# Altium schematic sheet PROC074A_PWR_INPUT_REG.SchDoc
size 431 x 279 mm; Date: Not shown in title block; ApprovedBy: Not shown in title block; CheckedBy: Not shown in title block; Author: Not shown in title block; CompanyName: Not shown in title block; Engineer: Not shown in title block; Organization: Not shown in title block; Address1: Not shown in title block; Address2: Not shown in title block; Address3: Not shown in title block; Address4: Not shown in title block; DocumentNumber: 1; Revision: Use project parameter SCH_Rev; SheetNumber: 5; SheetTotal: 22; PageSetup: Record=PageOptions¦CenterHorizontal=True¦CenterVertical=True¦PrintScale=1.00¦XCorrection=1.00¦YCorrection=1.00¦PrintKind=0¦BorderSize=5000000¦LeftOffset=0¦BottomOffset=0¦Orientation=2¦PaperLength=1000¦PaperWidth=1000¦Scale=100¦PaperSource=15¦PrintQuality=600¦MediaType=1¦DitherType=10¦PaperKind=Letter¦PrintScaleMode=1
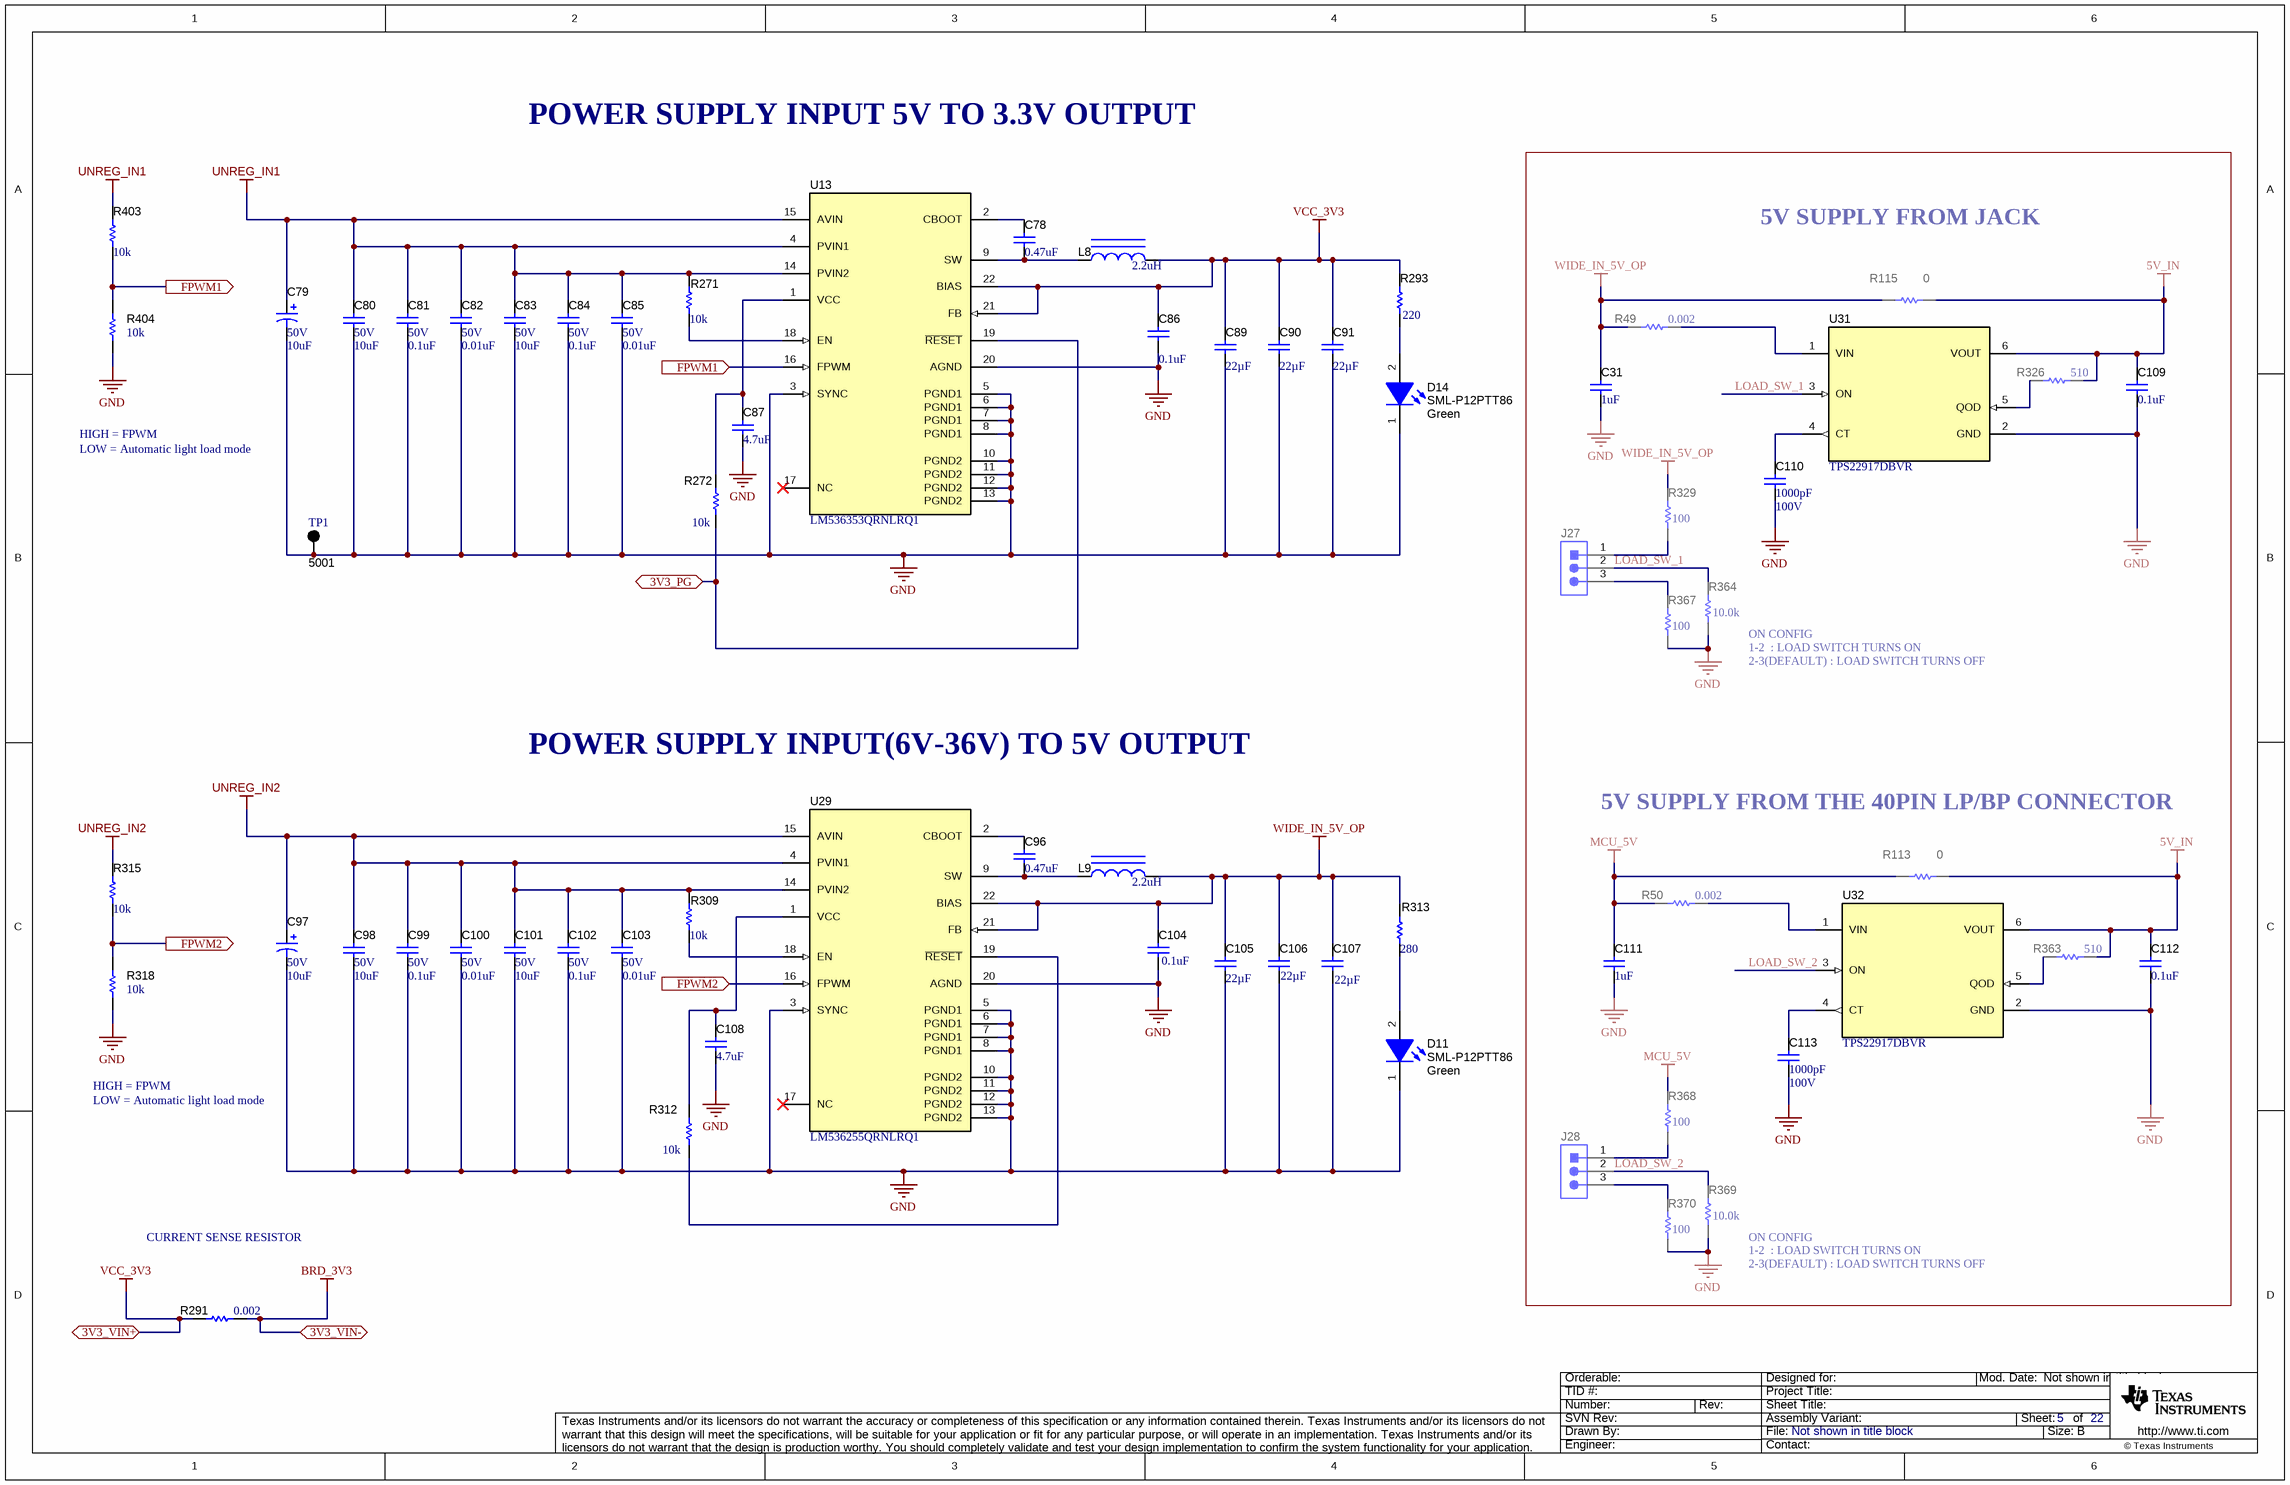
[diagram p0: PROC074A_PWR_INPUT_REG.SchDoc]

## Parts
C31  ValueDisplayed: 1uF  [0603]  (hidden comment: GCM188R71C105KA64D)
C78  ValueDisplayed: 0.47uF  [0402]  (hidden comment: JMK105B7474KVHF)
C79  VDC_V: 50V  ValueDisplayed: 10uF  [SM_RADIAL_C]  (hidden comment: EEE-FK1H100UR)
C80  VDC_V: 50V  ValueDisplayed: 10uF  [1210_270]  (hidden comment: GRM32ER71H106MA12)
C81  VDC_V: 50V  ValueDisplayed: 0.1uF  [1210]  (hidden comment: C1210C104K5RACTU)
C82  VDC_V: 50V  ValueDisplayed: 0.01uF  [0805_HV]  (hidden comment: C0805C103K5RACTU)
C83  VDC_V: 50V  ValueDisplayed: 10uF  [1210_270]  (hidden comment: GRM32ER71H106MA12)
C84  VDC_V: 50V  ValueDisplayed: 0.1uF  [1210]  (hidden comment: C1210C104K5RACTU)
C85  VDC_V: 50V  ValueDisplayed: 0.01uF  [0805_HV]  (hidden comment: C0805C103K5RACTU)
C86  ValueDisplayed: 0.1uF  [0402]  (hidden comment: 0402YC104KAT2A)
C87  ValueDisplayed: 4.7uF  [0805_HV]  (hidden comment: C2012X7R1E475K125AB)
C89  ValueDisplayed: 22µF  [1210_270]  (hidden comment: CL32B226KOJNFNE)
C90  ValueDisplayed: 22µF  [1210_270]  (hidden comment: CL32B226KOJNFNE)
C91  ValueDisplayed: 22µF  [1210_270]  (hidden comment: CL32B226KOJNFNE)
C96  ValueDisplayed: 0.47uF  [0402]  (hidden comment: JMK105B7474KVHF)
C97  VDC_V: 50V  ValueDisplayed: 10uF  [SM_RADIAL_C]  (hidden comment: EEE-FK1H100UR)
C98  VDC_V: 50V  ValueDisplayed: 10uF  [1210_270]  (hidden comment: GRM32ER71H106MA12)
C99  VDC_V: 50V  ValueDisplayed: 0.1uF  [1210]  (hidden comment: C1210C104K5RACTU)
C100  VDC_V: 50V  ValueDisplayed: 0.01uF  [0805_HV]  (hidden comment: C0805C103K5RACTU)
C101  VDC_V: 50V  ValueDisplayed: 10uF  [1210_270]  (hidden comment: GRM32ER71H106MA12)
C102  VDC_V: 50V  ValueDisplayed: 0.1uF  [1210]  (hidden comment: C1210C104K5RACTU)
C103  VDC_V: 50V  ValueDisplayed: 0.01uF  [0805_HV]  (hidden comment: C0805C103K5RACTU)
C104  ValueDisplayed: 0.1uF  [0402]  (hidden comment: 0402YC104KAT2A)
C105  ValueDisplayed: 22µF  [1210_270]  (hidden comment: CL32B226KOJNFNE)
C106  ValueDisplayed: 22µF  [1210_270]  (hidden comment: CL32B226KOJNFNE)
C107  ValueDisplayed: 22µF  [1210_270]  (hidden comment: CL32B226KOJNFNE)
C108  ValueDisplayed: 4.7uF  [0805_HV]  (hidden comment: C2012X7R1E475K125AB)
C109  ValueDisplayed: 0.1uF  [0603]  (hidden comment: C0603C104J3RACTU)
C110  VDC_V: 100V  ValueDisplayed: 1000pF  [0402]  (hidden comment: CGA2B3X7S2A102K050BB)
C111  ValueDisplayed: 1uF  [0603]  (hidden comment: GCM188R71C105KA64D)
C112  ValueDisplayed: 0.1uF  [0603]  (hidden comment: C0603C104J3RACTU)
C113  VDC_V: 100V  ValueDisplayed: 1000pF  [0402]  (hidden comment: CGA2B3X7S2A102K050BB)
D11  SML-P12PTT86  value Green  [SML-P1_GREEN]
D14  SML-P12PTT86  value Green  [SML-P1_GREEN]
J27  22284033  [Molex_0022284033]  (value not drawn)
J28  22284033  [Molex_0022284033]  (value not drawn)
L8  ValueDisplayed: 2.2uH  [XAL5030]  (hidden comment: XAL5030-222MEB)
L9  ValueDisplayed: 2.2uH  [XAL5030]  (hidden comment: XAL5030-222MEB)
R49  ValueDisplayed: 0.002  [1206]  (hidden comment: PMR18EZPFV2L00)
R50  ValueDisplayed: 0.002  [1206]  (hidden comment: PMR18EZPFV2L00)
R113  ValueDisplayed: 0  [2010]  (hidden comment: CRCW20100000Z0EF)
R115  ValueDisplayed: 0  [2010]  (hidden comment: CRCW20100000Z0EF)
R271  ValueDisplayed: 10k  [0402]  (hidden comment: CRCW040210K0JNED)
R272  ValueDisplayed: 10k  [0402]  (hidden comment: CRCW040210K0JNED)
R291  ValueDisplayed: 0.002  [1206]  (hidden comment: PMR18EZPFV2L00)
R293  ValueDisplayed: 220  [0402]  (hidden comment: CRCW0402220RJNED)
R309  ValueDisplayed: 10k  [0402]  (hidden comment: CRCW040210K0JNED)
R312  ValueDisplayed: 10k  [0402]  (hidden comment: CRCW040210K0JNED)
R313  ValueDisplayed: 280  [0402]  (hidden comment: CRCW0402280RFKED)
R315  ValueDisplayed: 10k  [0402]  (hidden comment: CRCW040210K0JNED)
R318  ValueDisplayed: 10k  [0402]  (hidden comment: CRCW040210K0JNED)
R326  ValueDisplayed: 510  [0402]  (hidden comment: CRCW0402510RJNED)
R329  ValueDisplayed: 100  [0402]  (hidden comment: ERJ-2GEJ101X)
R363  ValueDisplayed: 510  [0402]  (hidden comment: CRCW0402510RJNED)
R364  ValueDisplayed: 10.0k  [0402]  (hidden comment: CRCW040210K0FKED)
R367  ValueDisplayed: 100  [0402]  (hidden comment: ERJ-2GEJ101X)
R368  ValueDisplayed: 100  [0402]  (hidden comment: ERJ-2GEJ101X)
R369  ValueDisplayed: 10.0k  [0402]  (hidden comment: CRCW040210K0FKED)
R370  ValueDisplayed: 100  [0402]  (hidden comment: ERJ-2GEJ101X)
R403  ValueDisplayed: 10k  [0402]  (hidden comment: CRCW040210K0JNED)
R404  ValueDisplayed: 10k  [0402]  (hidden comment: CRCW040210K0JNED)
TP1  5001  [Keystone5001]
U13  LM536353QRNLRQ1  [RNL0022A]
U29  LM536255QRNLRQ1  [RNL0022A]
U31  TPS22917DBVR  [DBV0006A_L]
U32  TPS22917DBVR  [DBV0006A_L]

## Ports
3V3_PG, 3V3_VIN+, 3V3_VIN-, FPWM1 (in), FPWM1 (out), FPWM2 (in), FPWM2 (out)

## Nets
5V_IN: C109.1 C112.1 R113.2 R115.2 R326.1 R363.1 U31.6(VOUT) U32.6(VOUT)
BRD_3V3: R291.2 ; port 3V3_VIN-
GND: C31.2 C79.2(-) C80.2 C81.2 C82.2 C83.2 C84.2 C85.2 C86.2 C87.2 C89.2 C90.2 C91.2 C97.2(-) C98.2 C99.2 C100.2 C101.2 C102.2 C103.2 C104.2 C105.2 C106.2 C107.2 C108.2 C109.2 C110.2 C111.2 C112.2 C113.2 D11.1(K) D14.1(K) R318.1 R364.1 R367.1 R369.1 R370.1 R404.1 TP1.1 U13.3(SYNC) U13.5(PGND1) U13.6(PGND1) U13.7(PGND1) U13.8(PGND1) U13.10(PGND2) U13.11(PGND2) U13.12(PGND2) U13.13(PGND2) U13.20(AGND) U29.3(SYNC) U29.5(PGND1) U29.6(PGND1) U29.7(PGND1) U29.8(PGND1) U29.10(PGND2) U29.11(PGND2) U29.12(PGND2) U29.13(PGND2) U29.20(AGND) U31.2(GND) U32.2(GND)
MCU_5V: C111.1 R50.1 R113.1 R368.2
UNREG_IN1: C79.1(+) C80.1 C81.1 C82.1 C83.1 C84.1 C85.1 R271.2 R403.2 U13.4(PVIN1) U13.14(PVIN2) U13.15(AVIN)
UNREG_IN2: C97.1(+) C98.1 C99.1 C100.1 C101.1 C102.1 C103.1 R309.2 R315.2 U29.4(PVIN1) U29.14(PVIN2) U29.15(AVIN)
VCC_3V3: C86.1 C89.1 C90.1 C91.1 L8.2 R291.1 R293.2 U13.21(FB) U13.22(BIAS) ; port 3V3_VIN+
WIDE_IN_5V_OP: C31.1 C104.1 C105.1 C106.1 C107.1 L9.2 R49.1 R115.1 R313.2 R329.2 U29.21(FB) U29.22(BIAS)
3V3_PG: R272.2 U13.19(~{RESET}) ; port 3V3_PG
FPWM1: R403.1 R404.2 U13.16(FPWM) ; port FPWM1
FPWM2: R315.1 R318.2 U29.16(FPWM) ; port FPWM2
LOAD_SW_1: J27.2 R364.2 U31.3(ON)
LOAD_SW_2: J28.2 R369.2 U32.3(ON)
NetC78_1: C78.1 U13.2(CBOOT)
NetC78_2: C78.2 L8.1 U13.9(SW)
NetC87_1: C87.1 R272.1 U13.1(VCC)
NetC96_1: C96.1 U29.2(CBOOT)
NetC96_2: C96.2 L9.1 U29.9(SW)
NetC108_1: C108.1 R312.1 U29.1(VCC)
NetC110_1: C110.1 U31.4(CT)
NetC113_1: C113.1 U32.4(CT)
NetD11_2: D11.2(A) R313.1
NetD14_2: D14.2(A) R293.1
NetJ27_1: J27.1 R329.1
NetJ27_3: J27.3 R367.2
NetJ28_1: J28.1 R368.1
NetJ28_3: J28.3 R370.2
NetR49_2: R49.2 U31.1(VIN)
NetR50_2: R50.2 U32.1(VIN)
NetR271_1: R271.1 U13.18(EN)
NetR309_1: R309.1 U29.18(EN)
NetR312_2: R312.2 U29.19(~{RESET})
NetR326_2: R326.2 U31.5(QOD)
NetR363_2: R363.2 U32.5(QOD)

Not connected (* = marked no-connect by the designer): U13 17(NC)*; U29 17(NC)*

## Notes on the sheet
- POWER SUPPLY INPUT 5V TO 3.3V OUTPUT
- 5V SUPPLY FROM JACK
- HIGH = FPWM
- LOW = Automatic light load mode
- (near R364) ON CONFIG
- (near R364) 2-3(DEFAULT) : LOAD SWITCH TURNS OFF
- (near R364) 1-2  : LOAD SWITCH TURNS ON
- POWER SUPPLY INPUT(6V-36V) TO 5V OUTPUT
- 5V SUPPLY FROM THE 40PIN LP/BP CONNECTOR
- CURRENT SENSE RESISTOR
- (near R369) ON CONFIG
- (near R369) 2-3(DEFAULT) : LOAD SWITCH TURNS OFF
- (near R369) 1-2  : LOAD SWITCH TURNS ON

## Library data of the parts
C31 C111 = CMP-0007136-5: CAP, CERM, 1 uF, 16 V, +/- 10%, X7R, AEC-Q200 Grade 1, 0603; Manufacturer: MuRata; TaMin_C: -55°C; Polarized: N; SizeAreaWB_mm2: 4.68; Value1: Unknown; U/M: EA; Value: 1uF; TaMax_C: 125°C; SizeZ_mm: 1; SizeX_mm: 1.6; SizeY_mm: 0.8; Value2: 16V; SizeArea_mm2: 1.28; CompType: Capacitor; AEC Qualified: Y; Cap_F: 1µF; AEC Category: Q200
C78 C96 = CMP-0006717-2: CAP, CERM, 0.47 uF, 6.3 V, +/- 10%, X7R, 0402; Manufacturer: Taiyo Yuden; TaMin_C: -55°C; Polarized: N; SizeAreaWB_mm2: 3; Value1: Unknown; U/M: EA; Value: 0.47uF; TaMax_C: 125°C; SizeZ_mm: 0.6; SizeX_mm: 1; SizeY_mm: 0.5; Value2: 6.3V; CompType: Capacitor; Cap_F: 470nF; AEC Category: Q200
C79 C97 = CMP-0011176-2: CAP, AL, 10 uF, 50 V, +/- 20%, 1.52 ohm, AEC-Q200 Grade 2, SMD; Manufacturer: Panasonic; TaMin_C: -55°C; ESR_ohm: 1.52; Polarized: Y; SizeAreaWB_mm2: 62.05; U/M: EA; Value: 10uF; TaMax_C: 105°C; SizeZ_mm: 5.4; SizeX_mm: 6.5; SizeY_mm: 5.3; Cap_Case: C; SizeArea_mm2: 34.45; CompType: Capacitor; Cap_F: 10µF; IRMS_A: 85mA; AEC Grade: 2; AEC Category: Q200
C80 C83 C98 C101 = CMP-0009227-2: CAP, CERM, 10 uF, 50 V, +/- 20%, X7R, 1210; Manufacturer: MuRata; TaMin_C: -55°C; Polarized: N; SizeAreaWB_mm2: 14.7; Value1: Unknown; U/M: EA; Value: 10uF; TaMax_C: 125°C; SizeZ_mm: 2.7; SizeX_mm: 3.2; SizeY_mm: 2.5; Cap_Case: 1210; SizeArea_mm2: 8; Cap_F: 10µF; AEC Category: Q200
C81 C84 C99 C102 = CMP-0009075-1: CAP, CERM, 0.1 uF, 50 V, +/- 10%, X7R, 1210; Manufacturer: Kemet; TaMin_C: -55°C; Polarized: N; SizeAreaWB_mm2: 14.7; Value1: Unknown; U/M: EA; Value: 0.1uF; TaMax_C: 125°C; SizeZ_mm: 1.35; SizeX_mm: 3.2; SizeY_mm: 2.5; SizeArea_mm2: 8; Cap_F: 100nF; AEC Category: Q200
C82 C85 C100 C103 = CMP-0007718-2: CAP, CERM, 0.01 uF, 50 V, +/- 10%, X7R, 0805; Manufacturer: Kemet; TaMin_C: -55°C; ESR_ohm: 1.739; Polarized: N; SizeAreaWB_mm2: 6.75; Value1: 1.739 ohm; U/M: EA; Value: 0.01uF; TaMax_C: 125°C; SizeZ_mm: 1.45; SizeX_mm: 2; SizeY_mm: 1.25; Cap_Case: 0805; SizeArea_mm2: 2.5; Cap_F: 10nF; IRMS_A: 4.11dA; AEC Category: Q200
C86 C104 = CMP-0006201-2: CAP, CERM, 0.1 uF, 16 V, +/- 10%, X7R, 0402; Manufacturer: AVX; TaMin_C: -55°C; Polarized: N; SizeAreaWB_mm2: 3; Value1: Unknown; U/M: EA; Value: 0.1uF; TaMax_C: 125°C; SizeZ_mm: 0.6; SizeX_mm: 1; SizeY_mm: 0.5; Value2: 16V; CompType: Capacitor; Cap_F: 100nF; AEC Category: Q200
C87 C108 = CMP-0007870-2: CAP, CERM, 4.7 uF, 25 V, +/- 10%, X7R, 0805; Manufacturer: TDK; TaMin_C: -55°C; Polarized: N; SizeAreaWB_mm2: 6.75; Value1: Unknown; U/M: EA; Value: 4.7uF; TaMax_C: 125°C; SizeZ_mm: 1.45; SizeX_mm: 2; SizeY_mm: 1.25; Cap_Case: 0805; Value2: 25V; SizeArea_mm2: 2.5; CompType: Capacitor; Cap_F: 4.7µF; AEC Category: Q200
C89-C91 C105-C107 = CMP-0081783-1: CAP, CERM, 22 µF, 16 V,+/- 10%, X7R, 1210; Manufacturer: Samsung; TaMin_C: -55°C; Polarized: N; SizeAreaWB_mm2: 14.7; U/M: EA; Value: 22uF; TaMax_C: 125°C; SizeZ_mm: 2.7; SizeX_mm: 3.2; SizeY_mm: 2.5; Cap_Case: 1210; Value2: 16V; SizeArea_mm2: 8; CompType: Capacitor; AEC Category: Q200
C109 C112 = CMP-0006856-6: CAP, CERM, 0.1 uF, 25 V, +/- 5%, X7R, 0603; Manufacturer: Kemet; TaMin_C: -55°C; Polarized: N; SizeAreaWB_mm2: 4.68; Value1: Unknown; U/M: EA; Value: 0.1uF; TaMax_C: 125°C; SizeZ_mm: 1; SizeX_mm: 1.6; SizeY_mm: 0.8; Value2: 25V; SizeArea_mm2: 1.28; CompType: Capacitor; Cap_F: 100nF; AEC Category: Q200
C110 C113 = CMP-0006332-2: CAP, CERM, 1000 pF, 100 V, +/- 10%, X7S, AEC-Q200 Grade 1, 0402; Manufacturer: TDK; TaMin_C: -55°C; ESR_ohm: 2.71151; Polarized: N; SizeAreaWB_mm2: 3; Value1: 2.71151 ohm; U/M: EA; Value: 1000pF; TaMax_C: 125°C; SizeZ_mm: 0.6; SizeX_mm: 1; SizeY_mm: 0.5; AEC Qualified: Y; Cap_F: 1nF; IRMS_A: 2.64589dA; AEC Category: Q200
D11 D14 = CMP-0002873-1: LED, Green, SMD; Manufacturer: Rohm; Io_A: 20mA; Value1: W; U/M: EA; Vf_V: 2.2V; Type: AlInGaP
J27 J28 = CMP-0055332-1: Header, 2.54mm, 3x1, Tin, TH; Manufacturer: Molex; CNHeader: TRUE; Current_A: 4A; Shrouded: N; Gender: Male; Voltage_V: 250V; Row_Count: 1; Pitch_mm: 2.54; CT: FALSE; Cert_UL: Y
L8 L9 = CMP-0061001-1: Inductor, Shielded, Composite, 2.2 uH, 9.2 A, 0.01 ohm, SMD; Manufacturer: Coilcraft; Isat: 12.9A @ 30% inductance drop; Irms: 9.2A @ 40C rise; Green_Lifecycle: Not Set; SizeAreaWB_mm2: 54.4544; DCR_ohm: 0.01; Green_REACh: Incomplete; Value: 2.2uH; Imax_A: 9.2A; SizeZ_mm: 3.1; SizeX_mm: 5.28; SizeY_mm: 5.48; SizeArea_mm2: 28.9344; Ind_H: 2.2µH; AEC Category: Q200
R49 R50 = CMP-0081623-1: RES, 0.002, 1%, 1 W, AEC-Q200 Grade 0, 1206; Manufacturer: Rohm; Value_Code: 2L000; SizeAreaWB_mm2: 10.92; SizeArea_mm2: 5.12; AEC Qualified: Y; AEC Category: Q200; Res_ohm: 2m; Value: 0.002; SizeZ_mm: 1.35; Green_REACh: Incomplete; TempCo: 100 ppm/C; AEC Grade: 0; Power_W: 1W; SizeY_mm: 1.6; Green_Lifecycle: Active; CompType: Resistor; SizeX_mm: 3.2; INSTALLATION: DNP
R113 R115 = CMP-0016044-2: RES, 0, 5%, 0.75 W, AEC-Q200 Grade 0, 2010; Manufacturer: Vishay-Dale; Power_W: 750mW; TempCo: ppm/C; Value_Code: 0000; U/M: EA; Value: 0; EIA_Code: E24; SizeX_mm: 5; SizeY_mm: 2.5; SizeZ_mm: 1.66; Value2: 0.75W; SizeArea_mm2: 12.5; CompType: Resistor; AEC Qualified: Y; AEC Category: Q200; INSTALLATION: DNP
R271 R272 R309 R312 R315 R403 = CMP-0026825-5: RES, 10 k, 5%, 0.063 W, AEC-Q200 Grade 0, 0402; Manufacturer: Vishay-Dale; Power_W: 63mW; TempCo: 200 ppm/C; Value_Code: 10k0; Value: 10k; EIA_Code: E24; SizeX_mm: 1; SizeY_mm: 0.5; SizeZ_mm: 0.6; Value2: 0.063W; AEC Qualified: Y; VDC_V: 50V; AEC Category: Q200; AEC Grade: 0
R291 = CMP-0081623-1: RES, 0.002, 1%, 1 W, AEC-Q200 Grade 0, 1206; Manufacturer: Rohm; Value_Code: 2L000; SizeAreaWB_mm2: 10.92; SizeArea_mm2: 5.12; AEC Qualified: Y; AEC Category: Q200; Res_ohm: 2m; Value: 0.002; SizeZ_mm: 1.35; Green_REACh: Incomplete; TempCo: 100 ppm/C; AEC Grade: 0; Power_W: 1W; SizeY_mm: 1.6; Green_Lifecycle: Active; SizeX_mm: 3.2
R293 = CMP-0026878-3: RES, 220, 5%, 0.063 W, AEC-Q200 Grade 0, 0402; Manufacturer: Vishay-Dale; Power_W: 63mW; TempCo: 200 ppm/C; Value_Code: 220R; Value: 220; EIA_Code: E24; SizeX_mm: 1; SizeY_mm: 0.5; SizeZ_mm: 0.6; Value2: 0.063W; AEC Qualified: Y; VDC_V: 50V; AEC Category: Q200; AEC Grade: 0
R313 = CMP-0026216-2: RES, 280, 1%, 0.063 W, AEC-Q200 Grade 0, 0402; Manufacturer: Vishay-Dale; Power_W: 63mW; TempCo: 100 ppm/C; Value_Code: 280R; Value: 280; EIA_Code: E96; SizeX_mm: 1; SizeY_mm: 0.5; SizeZ_mm: 0.6; Value2: 0.063W; AEC Qualified: Y; VDC_V: 50V; AEC Category: Q200; AEC Grade: 0
R318 R404 = CMP-0026825-5: RES, 10 k, 5%, 0.063 W, AEC-Q200 Grade 0, 0402; Manufacturer: Vishay-Dale; Power_W: 63mW; TempCo: 200 ppm/C; Value_Code: 10k0; Value: 10k; EIA_Code: E24; SizeX_mm: 1; SizeY_mm: 0.5; SizeZ_mm: 0.6; Value2: 0.063W; CompType: Resistor; AEC Qualified: Y; VDC_V: 50V; AEC Category: Q200; AEC Grade: 0; INSTALLATION: DNP
R326 R363 = CMP-0026944-3: RES, 510, 5%, 0.063 W, AEC-Q200 Grade 0, 0402; Manufacturer: Vishay-Dale; Power_W: 63mW; TempCo: 200 ppm/C; Value_Code: 510R; Value: 510; EIA_Code: E24; SizeX_mm: 1; SizeY_mm: 0.5; SizeZ_mm: 0.6; Value2: 0.063W; AEC Qualified: Y; VDC_V: 50V; AEC Category: Q200; AEC Grade: 0
R329 R367 R368 R370 = CMP-0026993-2: RES, 100, 5%, 0.1 W, AEC-Q200 Grade 0, 0402; Manufacturer: Panasonic; Power_W: 100mW; TempCo: 200 ppm/C; Value_Code: 100R; U/M: EA; Value: 100; EIA_Code: E24; SizeX_mm: 1; SizeY_mm: 0.5; SizeZ_mm: 0.6; Value2: 0.1W; AEC Qualified: Y; AEC Grade: 0; AEC Category: Q200
R364 R369 = CMP-0025958-3: RES, 10.0 k, 1%, 0.063 W, AEC-Q200 Grade 0, 0402; Manufacturer: Vishay-Dale; Power_W: 63mW; TempCo: 100 ppm/C; Value_Code: 10k0; Value: 10.0k; EIA_Code: E96; Res_ohm: 10k; SizeX_mm: 1; SizeY_mm: 0.5; SizeZ_mm: 0.6; Value2: 0.063W; AEC Qualified: Y; VDC_V: 50V; AEC Category: Q200; AEC Grade: 0
TP1 = CMP-0055138-1: Test Point, Miniature, Black, TH; Manufacturer: Keystone; CNHeader: FALSE; Green_Lifecycle: Active; Green_REACh: Passed; ContactFinish: Silver; CT: TRUE
U13 = CMP-0076352-4: 3.5A, 36 V Synchronous, 2.1MHz, Automotive Step Down DC-DC Converter, RNL0022A (VQFN-HR-22); Manufacturer: Texas Instruments; SizeX_mm: 4.0; SizeY_mm: 5.0; CompType: IC; SizeZ_mm: 0.9; SizeArea_mm2: 20.0; SizeAreaWB_mm2: 42.0; AEC Category: Q200; AEC Qualified: Y
U29 = CMP-0076347-4: 2.5A, 36 V Synchronous, 2.1MHz, Automotive Step Down DC-DC Converter, RNL0022A (VQFN-HR-22); Manufacturer: Texas Instruments; Alternate PartNumber: LM536255QRNLTQ1; SizeX_mm: 4.0; SizeY_mm: 5.0; CompType: IC; SizeZ_mm: 0.9; SizeArea_mm2: 20.0; SizeAreaWB_mm2: 42.0; AEC Category: Q200; AEC Qualified: Y
U31 U32 = CMP-0077265-1: 5.5-V, 2-A, 80 mohm Low Leakage Load Switch with RCB and Programmable Rise Time, DBV0006A (SOT-23-6); Alternate PartNumber: TPS22917DBVT; Alternate Manufacturer: Texas Instruments; SizeAreaWB_mm2: 14.82; SizeZ_mm: 1.45; SizeX_mm: 2.8; SizeY_mm: 2.9; SizeArea_mm2: 8.12; CompType: IC; AEC Qualified: N; AEC Category: Q200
